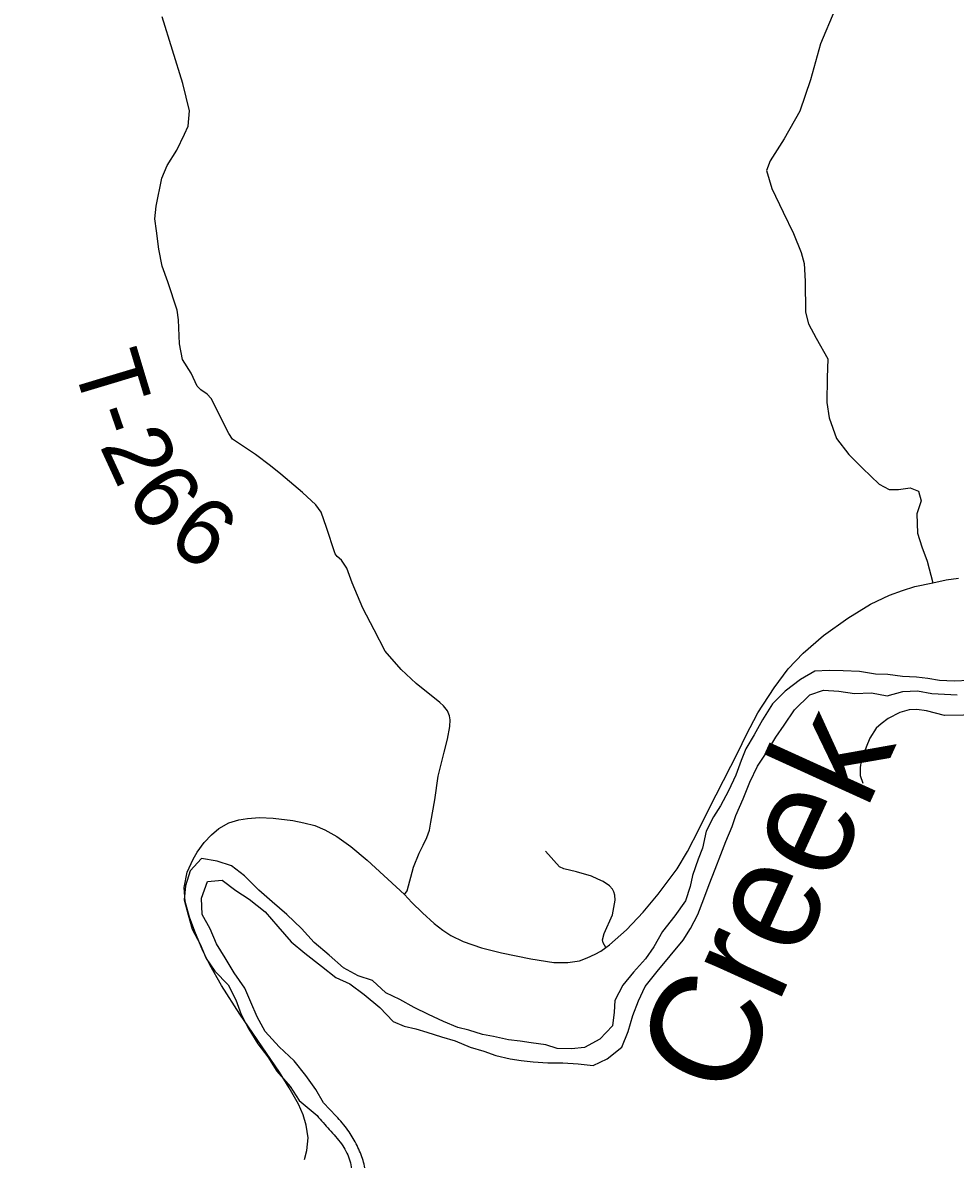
# Model space of a CAD drawing. Extents: x -10 to 158, y 8 to 33.
# Drawn here: x 130.537 to 131.336, y 29.998 to 30.972 of the extents above; entities that cross this region are included whole.
import ezdxf

# ---------------------------------------------------------------- set-up
doc = ezdxf.new("R2010")
doc.units = 0
for name, color, linetype in [('GM_X_County_Road', 7, 'Continuous'), ('GM_X_Major_River', 7, 'Continuous'), ('GM_X_Major_River_Text', 7, 'Continuous'), ('GM_X_State_Route', 7, 'Continuous'), ('GM_X_Township_Road', 7, 'Continuous'), ('GM_X_Township_Road_Text', 7, 'Continuous')]:
    doc.layers.add(name, color=color, linetype=linetype)

msp = doc.modelspace()

# ---------------------------------------------------------------- linework, layer by layer
at = {"layer": 'GM_X_County_Road'}
msp.add_lwpolyline([(131.2332, 30.98308), (131.22105, 30.95407), (131.21237, 30.92307), (131.2032, 30.89629), (131.1899, 30.87246), (131.17766, 30.85364), (131.17468, 30.84546), (131.17915, 30.82984), (131.18906, 30.80976), (131.19774, 30.79141), (131.20444, 30.77504), (131.20692, 30.76562), (131.20766, 30.75049), (131.20816, 30.72396), (131.21064, 30.7138), (131.21708, 30.70165), (131.22725, 30.68404), (131.22675, 30.66768), (131.22626, 30.64635), (131.22824, 30.63346), (131.23469, 30.6156), (131.24535, 30.60197), (131.257, 30.59006), (131.27114, 30.57643), (131.27982, 30.57196), (131.28775, 30.57196), (131.29767, 30.5732), (131.30486, 30.57047), (131.30709, 30.56229), (131.30362, 30.55113), (131.3041, 30.53431), (131.30782, 30.52277), (131.31228, 30.51032), (131.3173, 30.49184)], dxfattribs=at)
at = {"layer": 'GM_X_Major_River'}
for points in [[(131.34829, 30.40798), (131.33543, 30.40746), (131.32294, 30.40809), (131.31308, 30.40988), (131.30323, 30.41092), (131.29111, 30.41155), (131.27861, 30.41331), (131.26801, 30.41358), (131.25436, 30.41571), (131.24035, 30.41632), (131.22824, 30.41657), (131.21614, 30.41606), (131.20372, 30.4091), (131.19059, 30.3991), (131.17974, 30.38799), (131.17118, 30.37424), (131.16413, 30.36165), (131.15707, 30.34944), (131.15302, 30.33954), (131.14823, 30.32697), (131.14195, 30.31363), (131.13528, 30.30067), (131.12933, 30.29112), (131.12303, 30.27892), (131.11978, 30.26447), (131.1161, 30.25495), (131.11133, 30.24087), (131.10916, 30.23137), (131.10514, 30.21919), (131.09619, 30.2062), (131.08537, 30.19281), (131.07794, 30.17983), (131.07086, 30.16952), (131.06077, 30.15804), (131.05143, 30.14694), (131.04476, 30.1336), (131.04411, 30.12373)], [(131.10956, 30.19534), (131.11586, 30.20754), (131.12101, 30.22087), (131.12542, 30.23306), (131.13057, 30.24639), (131.13536, 30.25895), (131.13977, 30.26999), (131.14531, 30.28295), (131.14823, 30.29246), (131.15451, 30.30656), (131.16041, 30.32104), (131.16707, 30.33476), (131.17489, 30.3466), (131.18269, 30.35958), (131.18977, 30.36989), (131.19871, 30.38288), (131.21181, 30.39591), (131.2235, 30.39983), (131.23676, 30.39883), (131.25002, 30.39708), (131.26478, 30.39761), (131.27805, 30.3951), (131.29163, 30.39866), (131.30411, 30.39917), (131.31625, 30.39702), (131.33821, 30.39574)], [(131.04411, 30.12373), (131.04273, 30.11196), (131.03188, 30.10046), (131.01871, 30.09349), (131.00737, 30.09224), (130.99526, 30.09249), (130.98539, 30.0958), (130.97288, 30.09756), (130.9634, 30.09898), (130.95355, 30.10001), (130.94065, 30.10291), (130.93118, 30.1047), (130.9194, 30.10837), (130.90992, 30.11054), (130.89775, 30.11572), (130.88482, 30.12166), (130.87265, 30.12759), (130.86046, 30.13467), (130.84829, 30.14023), (130.83682, 30.15073), (130.82467, 30.15477), (130.8121, 30.16184), (130.79987, 30.17271), (130.78689, 30.18357), (130.77616, 30.19559), (130.76354, 30.2076), (130.75094, 30.21846), (130.73948, 30.2282), (130.72723, 30.24058), (130.71617, 30.24919), (130.70363, 30.25323), (130.69036, 30.25536), (130.68064, 30.24502), (130.67662, 30.23208), (130.67561, 30.21994), (130.67878, 30.20707), (130.68232, 30.19498), (130.68927, 30.18216), (130.69433, 30.16969), (130.70164, 30.15877), (130.71312, 30.14714), (130.71969, 30.13431), (130.72437, 30.12185), (130.73094, 30.10902), (130.73864, 30.09659), (130.74709, 30.0853), (130.75479, 30.07325), (130.76629, 30.0601), (130.77397, 30.04808), (130.78943, 30.03503)], [(130.80575, 30.03456), (130.79497, 30.04609), (130.78827, 30.0573), (130.77981, 30.06934), (130.76983, 30.08213), (130.75683, 30.09413), (130.74496, 30.10728), (130.73801, 30.11972), (130.73258, 30.13218), (130.72753, 30.14426), (130.7183, 30.15743), (130.71059, 30.17025), (130.70327, 30.18231), (130.69783, 30.19514), (130.69089, 30.20758), (130.69035, 30.22161), (130.6955, 30.2357), (130.70797, 30.23697), (130.7198, 30.22799), (130.73124, 30.22053), (130.74498, 30.20967), (130.75571, 30.19727), (130.76721, 30.18412), (130.77904, 30.17439), (130.79317, 30.16316), (130.80538, 30.15343), (130.81755, 30.14787), (130.82976, 30.1389), (130.84313, 30.12766), (130.85461, 30.11565), (130.86412, 30.11157), (130.87398, 30.1094), (130.88347, 30.10647), (130.89601, 30.10243), (130.90777, 30.09914), (130.9207, 30.09359), (130.93247, 30.09031), (130.94272, 30.08662), (130.95486, 30.08371), (130.96434, 30.0823), (130.97457, 30.08127), (130.98707, 30.08027), (130.99993, 30.0804), (131.01319, 30.0794), (131.02607, 30.07803), (131.03812, 30.08384), (131.0505, 30.09383), (131.05603, 30.10717), (131.06004, 30.12086), (131.06482, 30.13343), (131.07074, 30.14563), (131.08082, 30.15863), (131.10323, 30.18541), (131.10956, 30.19534)]]:
    msp.add_lwpolyline(points, dxfattribs=at)
for points in [[(130.78943, 30.03503), (130.79988, 30.02306), (130.81033, 30.01071), (130.81701, 29.99791), (130.81914, 29.98427), (130.81784, 29.9721), (130.81426, 29.9595), (130.80727, 29.94685), (130.79726, 29.93376), (130.78532, 29.92254), (130.77226, 29.90978), (130.75919, 29.89816), (130.74947, 29.88964), (130.7379, 29.87918), (130.72634, 29.86759), (130.71438, 29.85751), (130.70125, 29.8493), (130.68812, 29.84072), (130.67498, 29.83289), (130.66256, 29.82736), (130.65013, 29.82221), (130.63727, 29.82009), (130.62256, 29.81528), (130.60971, 29.81239), (130.59799, 29.81029), (130.58551, 29.80817), (130.57267, 29.80491), (130.561, 29.79977), (130.5475, 29.79081), (130.53707, 29.77999), (130.52476, 29.76762), (130.51205, 29.75715), (130.49899, 29.74477), (130.487, 29.73621), (130.47374, 29.73521), (130.46116, 29.73841), (130.44747, 29.74046), (130.43449, 29.74555), (130.42184, 29.75292), (130.40923, 29.7584), (130.39657, 29.76654), (130.38507, 29.77356), (130.37284, 29.77866), (130.35953, 29.78033), (130.35004, 29.78054), (130.33673, 29.78259), (130.32229, 29.78424), (130.30783, 29.78703), (130.29485, 29.79136), (130.28307, 29.79306), (130.2709, 29.79436), (130.25919, 29.79188), (130.24941, 29.78715), (130.23812, 29.78164), (130.22654, 29.77156), (130.21802, 29.75964), (130.21022, 29.75002), (130.20174, 29.7362), (130.19666, 29.72281), (130.19153, 29.71247), (130.18833, 29.70026), (130.18895, 29.6866), (130.19182, 29.67412), (130.19583, 29.66165), (130.19793, 29.65029), (130.20045, 29.63628), (130.20258, 29.62265), (130.20736, 29.60944), (130.21365, 29.59664), (130.2192, 29.58344), (130.22359, 29.5706), (130.22798, 29.55853), (130.23237, 29.54569), (130.23296, 29.53354), (130.23735, 29.52109), (130.24249, 29.50902), (130.24916, 29.4966), (130.2543, 29.48454), (130.26476, 29.47219), (130.27709, 29.46101), (130.28527, 29.44899), (130.29575, 29.43512), (130.30014, 29.42267), (130.30224, 29.41093), (130.30585, 29.3996), (130.30496, 29.38553), (130.30063, 29.37254), (130.29478, 29.35991), (130.28513, 29.34797), (130.27316, 29.33826), (130.26042, 29.32931), (130.24727, 29.32186), (130.23488, 29.31481), (130.22019, 29.30886), (130.20701, 29.30294), (130.19235, 29.29546), (130.17914, 29.29144)], [(130.21251, 29.29202), (130.22531, 29.29756), (130.237, 29.30194), (130.24715, 29.30705), (130.25881, 29.31257), (130.27235, 29.31926), (130.28477, 29.32479), (130.29709, 29.3364), (130.30561, 29.34832), (130.31373, 29.361), (130.31916, 29.37628), (130.3216, 29.38848), (130.3229, 29.40103), (130.32158, 29.41127), (130.31717, 29.42486), (130.3109, 29.43615), (130.30349, 29.44817), (130.29645, 29.4602), (130.28643, 29.46953), (130.27561, 29.48073), (130.26441, 29.49231), (130.25927, 29.50438), (130.25413, 29.51606), (130.2505, 29.52853), (130.2469, 29.5391), (130.24441, 29.55159), (130.24036, 29.56633), (130.2356, 29.57803), (130.23006, 29.59122), (130.22529, 29.60405), (130.22128, 29.61614), (130.21807, 29.62634), (130.21329, 29.63917), (130.21122, 29.64939), (130.20835, 29.66149), (130.20666, 29.67133), (130.20493, 29.68346), (130.20508, 29.69713), (130.20562, 29.70968), (130.20958, 29.7219), (130.21466, 29.7349), (130.22315, 29.74834), (130.23205, 29.76027), (130.24325, 29.77072), (130.25564, 29.77777), (130.26734, 29.78101), (130.28026, 29.77971), (130.29209, 29.77574), (130.30584, 29.77066), (130.31804, 29.76708), (130.33136, 29.76465), (130.34161, 29.76407), (130.35489, 29.76354), (130.3686, 29.76074), (130.37886, 29.7594), (130.39222, 29.75507), (130.40447, 29.74845), (130.41634, 29.7422), (130.42784, 29.73518), (130.43971, 29.72855), (130.45346, 29.72347), (130.46718, 29.71953), (130.48042, 29.72166), (130.49439, 29.7257), (130.50759, 29.7301), (130.52069, 29.73983), (130.53109, 29.75254), (130.54186, 29.76602), (130.55149, 29.7791), (130.56538, 29.7877), (130.59036, 29.79117), (130.60582, 29.79637), (130.61903, 29.80002), (130.63261, 29.80443), (130.64277, 29.80879), (130.65675, 29.81245), (130.66693, 29.81566), (130.68011, 29.82121), (130.69289, 29.82789), (130.70528, 29.8357), (130.71916, 29.8443), (130.73151, 29.85362), (130.74007, 29.86327), (130.75315, 29.87489), (130.76549, 29.88498), (130.77892, 29.89774), (130.79124, 29.90935), (130.80279, 29.92132), (130.81281, 29.93403), (130.82016, 29.94745), (130.82676, 29.96048), (130.83035, 29.97231), (130.83088, 29.98524), (130.82838, 29.99811), (130.82285, 30.01092), (130.81582, 30.02258), (130.80575, 30.03456)]]:
    msp.add_spline(points, degree=3, dxfattribs=at)
at = {"layer": 'GM_X_State_Route'}
msp.add_lwpolyline([(130.77867, 29.99744), (130.78067, 30.00507), (130.78167, 30.01607), (130.78013, 30.02688), (130.77749, 30.0357), (130.77349, 30.04497), (130.76559, 30.05897), (130.75731, 30.07233), (130.72323, 30.12204), (130.70742, 30.14649), (130.69751, 30.16431), (130.6916, 30.17631), (130.68451, 30.19276), (130.68015, 30.2053), (130.67642, 30.21857), (130.67561, 30.23066), (130.67806, 30.24365), (130.68318, 30.25483), (130.6866, 30.26101), (130.69251, 30.2691), (130.69878, 30.27574), (130.70533, 30.28119), (130.71387, 30.2861), (130.72223, 30.28864), (130.72978, 30.28992), (130.73995, 30.29055), (130.75186, 30.2901), (130.76859, 30.28819), (130.77804, 30.28619), (130.78749, 30.28364), (130.79594, 30.2801), (130.80639, 30.27428), (130.81839, 30.26565), (130.8323, 30.25411), (130.8643, 30.22447), (130.87074, 30.21766), (130.87965, 30.20884), (130.88983, 30.19966), (130.8971, 30.19394), (130.9041, 30.18939), (130.91473, 30.18421), (130.93027, 30.17885), (130.94763, 30.17467), (130.97263, 30.16931), (130.99235, 30.16631), (131.00426, 30.16631), (131.01435, 30.16776), (131.0208, 30.17022), (131.0278, 30.17331), (131.03261, 30.17603), (131.03689, 30.1793), (131.03998, 30.18139), (131.05461, 30.19439), (131.06888, 30.20939), (131.08188, 30.22493), (131.09796, 30.24665), (131.10705, 30.26147), (131.11705, 30.28083), (131.12532, 30.29764), (131.15022, 30.3469), (131.15713, 30.36117), (131.16731, 30.38035), (131.18113, 30.40189), (131.19331, 30.41816), (131.20612, 30.43143), (131.22348, 30.4467), (131.24447, 30.46169), (131.26383, 30.47351), (131.2801, 30.48114), (131.2911, 30.48542), (131.30173, 30.48869), (131.3173, 30.49184), (131.32873, 30.49441), (131.33936, 30.49578)], dxfattribs=at)
at = {"layer": 'GM_X_Township_Road'}
for points in [[(130.80503, 30.51685), (130.8045, 30.51761), (130.79737, 30.53918), (130.79293, 30.55241), (130.7883, 30.5588), (130.77683, 30.56925), (130.75823, 30.58517), (130.74944, 30.5923), (130.73648, 30.60201), (130.71704, 30.61516), (130.71371, 30.61997), (130.69863, 30.65004), (130.6953, 30.65365), (130.68984, 30.65745), (130.6866, 30.66059), (130.68142, 30.6717), (130.67392, 30.68327), (130.67161, 30.69678), (130.67056, 30.71746), (130.66939, 30.72556), (130.66148, 30.75006), (130.65652, 30.7635), (130.65375, 30.77785), (130.65162, 30.79358), (130.65023, 30.80385), (130.65156, 30.81495), (130.65632, 30.83892), (130.66078, 30.8497), (130.66912, 30.86293), (130.67574, 30.87645), (130.6789, 30.88349), (130.68005, 30.89658), (130.67444, 30.92002), (130.65663, 30.97725)], [(130.8643, 30.22447), (130.86665, 30.22775), (130.87218, 30.24805), (130.87701, 30.26001), (130.8802, 30.26701), (130.88356, 30.27356), (130.88574, 30.27974), (130.88692, 30.28673), (130.89038, 30.3058), (130.89331, 30.32597), (130.89838, 30.34676), (130.90113, 30.35787), (130.90317, 30.36871), (130.90353, 30.37448), (130.90291, 30.37795), (130.90122, 30.38203), (130.89775, 30.38639), (130.89456, 30.38923), (130.87421, 30.40549), (130.8615, 30.41758), (130.84773, 30.43321), (130.83822, 30.45152), (130.82874, 30.47023), (130.8194, 30.49179), (130.81486, 30.50429), (130.81042, 30.51141), (130.80663, 30.51456), (130.80503, 30.51685)], [(131.45051, 30.36894), (131.44219, 30.36996), (131.43175, 30.37154), (131.42517, 30.37286), (131.40052, 30.37687), (131.39112, 30.37768), (131.38081, 30.37795), (131.36602, 30.37882), (131.35444, 30.37865), (131.34347, 30.37839), (131.32723, 30.37803), (131.31179, 30.38198), (131.30363, 30.3833), (131.29696, 30.38304), (131.28888, 30.38058), (131.27905, 30.37558), (131.27282, 30.37093), (131.26879, 30.36715), (131.26317, 30.35855), (131.26001, 30.35101), (131.25589, 30.33925), (131.25483, 30.33346), (131.25483, 30.3267), (131.25712, 30.32003)], [(131.03689, 30.1793), (131.03471, 30.18321), (131.03398, 30.18585), (131.03561, 30.19112), (131.04261, 30.2073), (131.04498, 30.21984), (131.04461, 30.22402), (131.04379, 30.22684), (131.0427, 30.22929), (131.03998, 30.23211), (131.03471, 30.23575), (131.03016, 30.23765), (131.02453, 30.2402), (131.0118, 30.24393), (131.00104, 30.24664), (130.9973, 30.24834), (130.9853, 30.26183)]]:
    msp.add_lwpolyline(points, dxfattribs=at)

# ---------------------------------------------------------------- texts
at = {"layer": 'GM_X_Major_River_Text'}
msp.add_text('Creek', height=0.094685, rotation=65.53536, dxfattribs=at).set_placement((131.14628, 30.04599))
at = {"layer": 'GM_X_Township_Road_Text'}
for s, rotation, p in [('T', 286.7366, (130.57965, 30.68035)), ('-', 289.05227, (130.59266, 30.63727)), ('2', 294.72488, (130.60256, 30.60953)), ('6', 306.88324, (130.62392, 30.56647)), ('6', 324.8057, (130.65878, 30.52503))]:
    msp.add_text(s, height=0.05682, rotation=rotation, dxfattribs=at).set_placement(p)

doc.saveas('drawing.dxf')
